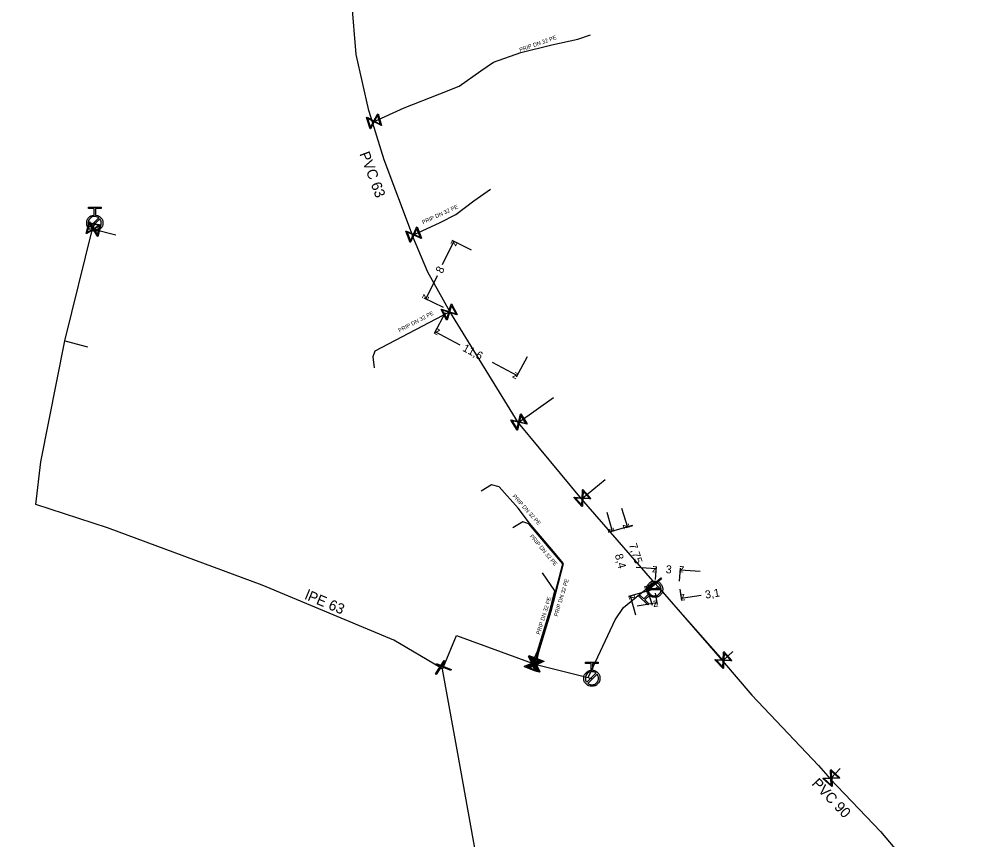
# Model space of a CAD drawing. Extents: x -641905 to -641246, y -1111750 to -1110210.
# Drawn here: x -641580.5 to -641459.9, y -1110405.6 to -1110303.2 of the extents above; entities that cross this region are included whole.
import ezdxf

# ---------------------------------------------------------------- set-up
doc = ezdxf.new("R2010")
doc.units = 0
for name, color, linetype in [('Default', 7, 'Continuous'), ('VP Hydrant', 7, 'Continuous'), ('VP Kótování', 7, 'Continuous'), ('VP Popis přípojky', 7, 'Continuous'), ('VP Přípojka', 7, 'Continuous'), ('VP Řad', 7, 'Continuous'), ('VP Řad - popis', 7, 'Continuous'), ('VP Šoupě', 7, 'Continuous')]:
    doc.layers.add(name, color=color, linetype=linetype)

msp = doc.modelspace()

# ---------------------------------------------------------------- linework, layer by layer
at = {"layer": 'Default'}
for points in [[(-641571, -1110327.63), (-641570.64, -1110327.66), (-641570.38, -1110327.92), (-641570.09, -1110328.21), (-641570.09, -1110328.63), (-641570.09, -1110329.04), (-641570.39, -1110329.34), (-641570.68, -1110329.63), (-641571.09, -1110329.63), (-641571.51, -1110329.63), (-641571.8, -1110329.34), (-641572.09, -1110329.04), (-641572.09, -1110328.63), (-641572.09, -1110328.21), (-641571.8, -1110327.92), (-641571.54, -1110327.66), (-641571.18, -1110327.63)], [(-641570.59, -1110327.99), (-641570.8, -1110327.81), (-641571.09, -1110327.81), (-641571.43, -1110327.81), (-641571.67, -1110328.05), (-641571.91, -1110328.29), (-641571.91, -1110328.63), (-641571.91, -1110328.92), (-641571.73, -1110329.13)], [(-641571.6, -1110329.26), (-641571.38, -1110329.44), (-641571.09, -1110329.44), (-641570.76, -1110329.44), (-641570.52, -1110329.2), (-641570.28, -1110328.96), (-641570.28, -1110328.63), (-641570.28, -1110328.34), (-641570.46, -1110328.12)], [(-641501.93, -1110374.99), (-641502.16, -1110374.72), (-641502.16, -1110374.35), (-641502.16, -1110373.94), (-641501.86, -1110373.64), (-641501.57, -1110373.35), (-641501.16, -1110373.35), (-641500.74, -1110373.36), (-641500.45, -1110373.65), (-641500.16, -1110373.94), (-641500.16, -1110374.36), (-641500.16, -1110374.77), (-641500.45, -1110375.06), (-641500.75, -1110375.36), (-641501.16, -1110375.36), (-641501.53, -1110375.36), (-641501.8, -1110375.12)], [(-641500.35, -1110374.27), (-641500.38, -1110373.99), (-641500.58, -1110373.78), (-641500.82, -1110373.55), (-641501.16, -1110373.54), (-641501.49, -1110373.54), (-641501.73, -1110373.78), (-641501.94, -1110373.99), (-641501.97, -1110374.26)], [(-641501.97, -1110374.44), (-641501.94, -1110374.72), (-641501.74, -1110374.93), (-641501.5, -1110375.17), (-641501.16, -1110375.17), (-641500.83, -1110375.17), (-641500.59, -1110374.93), (-641500.38, -1110374.73), (-641500.35, -1110374.45)], [(-641508.91, -1110384.47), (-641508.55, -1110384.5), (-641508.29, -1110384.76), (-641508, -1110385.06), (-641508, -1110385.47), (-641508, -1110385.89), (-641508.29, -1110386.18), (-641508.59, -1110386.47), (-641509, -1110386.47), (-641509.41, -1110386.47), (-641509.71, -1110386.18), (-641510, -1110385.89), (-641510, -1110385.47), (-641510, -1110385.06), (-641509.71, -1110384.76), (-641509.45, -1110384.5), (-641509.09, -1110384.47)], [(-641508.49, -1110384.83), (-641508.71, -1110384.66), (-641509, -1110384.66), (-641509.34, -1110384.66), (-641509.58, -1110384.89), (-641509.81, -1110385.13), (-641509.81, -1110385.47), (-641509.81, -1110385.76), (-641509.64, -1110385.98)], [(-641509.51, -1110386.11), (-641509.29, -1110386.28), (-641509, -1110386.28), (-641508.67, -1110386.28), (-641508.43, -1110386.04), (-641508.19, -1110385.81), (-641508.19, -1110385.47), (-641508.19, -1110385.18), (-641508.36, -1110384.96)]]:
    msp.add_open_spline(points, degree=3, dxfattribs=at)
at = {"layer": 'VP Hydrant'}
for points in [[(-641571.18, -1110327.63), (-641571.18, -1110326.81), (-641571.87, -1110326.81), (-641571.87, -1110326.63), (-641570.31, -1110326.63), (-641570.31, -1110326.81), (-641571, -1110326.81), (-641571, -1110327.63)], [(-641571.73, -1110329.13), (-641570.59, -1110327.99)], [(-641570.46, -1110328.12), (-641571.6, -1110329.26)], [(-641501.97, -1110374.26), (-641500.35, -1110374.27)], [(-641500.35, -1110374.45), (-641501.97, -1110374.44)], [(-641501.8, -1110375.12), (-641502.38, -1110375.7), (-641501.9, -1110376.19), (-641502.03, -1110376.32), (-641503.13, -1110375.21), (-641503, -1110375.08), (-641502.51, -1110375.57), (-641501.93, -1110374.99)], [(-641509.09, -1110384.47), (-641509.09, -1110383.65), (-641509.78, -1110383.65), (-641509.78, -1110383.47), (-641508.22, -1110383.47), (-641508.22, -1110383.65), (-641508.91, -1110383.65), (-641508.91, -1110384.47)], [(-641509.64, -1110385.98), (-641508.49, -1110384.83)], [(-641508.36, -1110384.96), (-641509.51, -1110386.11)]]:
    msp.add_lwpolyline(points, dxfattribs=at)
at = {"layer": 'VP Kótování'}
for points in [[(-641527.65, -1110333.8), (-641526.24, -1110330.92)], [(-641524.02, -1110332), (-641526.47, -1110330.81)], [(-641528.34, -1110335.23), (-641529.75, -1110338.11)], [(-641527.52, -1110339.19), (-641529.97, -1110338)], [(-641527.31, -1110339.85), (-641528.68, -1110342.42)], [(-641525.46, -1110343.86), (-641528.56, -1110342.2)], [(-641517.08, -1110345.32), (-641518.45, -1110347.89)], [(-641521.44, -1110346.01), (-641518.33, -1110347.67)], [(-641507.14, -1110364.72), (-641506.46, -1110367.12)], [(-641505.3, -1110364.24), (-641504.54, -1110366.62)], [(-641503.92, -1110366.41), (-641506.7, -1110367.19)], [(-641503.92, -1110366.42), (-641504.78, -1110366.7)], [(-641503.46, -1110371.59), (-641500.96, -1110371.76)], [(-641501.06, -1110373.16), (-641500.95, -1110371.52)], [(-641498.07, -1110373.36), (-641497.95, -1110371.72)], [(-641495.48, -1110372.14), (-641497.97, -1110371.97)], [(-641501.64, -1110374.49), (-641504.42, -1110375.27)], [(-641501.57, -1110373.81), (-641502.44, -1110374.08)], [(-641501.44, -1110376.39), (-641502.2, -1110374.01)], [(-641498.02, -1110374.35), (-641497.79, -1110375.77)], [(-641503.5, -1110377.61), (-641504.18, -1110375.21)], [(-641501.08, -1110374.85), (-641500.85, -1110376.26)], [(-641495.36, -1110375.12), (-641497.83, -1110375.52)], [(-641503.36, -1110376.42), (-641500.89, -1110376.02)]]:
    msp.add_lwpolyline(points, dxfattribs=at)
at = {"layer": 'VP Přípojka'}
for points in [[(-641536.4, -1110316.01), (-641536.21, -1110315.93), (-641532.46, -1110314.25), (-641528.01, -1110312.5), (-641525.58, -1110311.52), (-641522.87, -1110309.6), (-641521.28, -1110308.52), (-641517.88, -1110307.31), (-641514, -1110306.36), (-641510.76, -1110305.68), (-641509.19, -1110305.14)], [(-641531.42, -1110330.15), (-641531.27, -1110330.09), (-641527.94, -1110328.56), (-641526, -1110327.54), (-641523.75, -1110325.87), (-641521.67, -1110324.38)], [(-641571.14, -1110328.81), (-641571.13, -1110328.76), (-641571.1, -1110328.62)], [(-641571.39, -1110329.35), (-641571.25, -1110329.38), (-641568.48, -1110330.11)], [(-641526.74, -1110339.69), (-641526.83, -1110339.74), (-641536.12, -1110344.64), (-641536.37, -1110345.33), (-641536.18, -1110346.69)], [(-641574.84, -1110343.34), (-641574.68, -1110343.39), (-641572, -1110344.07)], [(-641518.19, -1110353.53), (-641518.11, -1110353.48), (-641513.79, -1110350.4)], [(-641515.97, -1110383.76), (-641515.61, -1110382.16), (-641514.07, -1110377.1), (-641512.53, -1110371.15), (-641514.26, -1110369.12), (-641516.81, -1110366.09), (-641518.21, -1110364.22), (-641520.59, -1110361.58), (-641521.53, -1110361.33), (-641522.82, -1110362.09)], [(-641510.28, -1110363.07), (-641510.18, -1110362.98), (-641507.36, -1110360.66)], [(-641516.18, -1110383.71), (-641515.71, -1110382.15), (-641514.17, -1110377.07), (-641512.64, -1110371.18), (-641514.34, -1110369.18), (-641516.87, -1110366.18), (-641517.64, -1110365.95), (-641518.87, -1110366.68)], [(-641516.46, -1110383.61), (-641515.81, -1110382.1), (-641514.26, -1110377.04), (-641513.64, -1110374.55), (-641515.19, -1110372.31)], [(-641501.23, -1110373.51), (-641501.09, -1110373.66), (-641492.62, -1110383.25)], [(-641500.78, -1110374.02), (-641501.16, -1110374.35)], [(-641492.67, -1110383.28), (-641492.57, -1110383.21), (-641491.41, -1110382.15)], [(-641509.46, -1110385.39), (-641509.26, -1110385.47), (-641509, -1110385.47)], [(-641479.24, -1110398.03), (-641479.1, -1110397.95), (-641478, -1110396.74)]]:
    msp.add_lwpolyline(points, dxfattribs=at)
at = {"layer": 'VP Řad'}
for points in [[(-641527.66, -1110384.33), (-641527.53, -1110384.09), (-641527.52, -1110384.06), (-641525.91, -1110380.13), (-641516.46, -1110383.61), (-641516.18, -1110383.71), (-641515.97, -1110383.76), (-641509.46, -1110385.39), (-641506.08, -1110378.16), (-641505.04, -1110376.65), (-641501.23, -1110373.51), (-641501.31, -1110373.41), (-641501.39, -1110373.32), (-641510.28, -1110363.07), (-641518.16, -1110353.57), (-641518.19, -1110353.53), (-641526.74, -1110339.69), (-641529.48, -1110334.78), (-641531.39, -1110330.24), (-641531.42, -1110330.15), (-641534.94, -1110320.75), (-641536.4, -1110316.01), (-641536.84, -1110314.59), (-641538.45, -1110307.59), (-641539, -1110300.99)], [(-641527.66, -1110384.33), (-641527.95, -1110384.14), (-641533.74, -1110380.7), (-641550.18, -1110373.84), (-641569.5, -1110366.69), (-641578.47, -1110363.78), (-641577.82, -1110358.43), (-641574.84, -1110343.34), (-641571.39, -1110329.35), (-641571.14, -1110328.81)], [(-641501.23, -1110373.51), (-641501.1, -1110373.66), (-641500.78, -1110374.02), (-641492.67, -1110383.28), (-641489.03, -1110387.57), (-641480.69, -1110396.36), (-641479.24, -1110398.03), (-641472.94, -1110404.61), (-641468.24, -1110410.18), (-641464.28, -1110416.05), (-641461.19, -1110422.75), (-641460.59, -1110426.23), (-641459.94, -1110433), (-641461.33, -1110445.88), (-641461.34, -1110445.94), (-641462.79, -1110455.16), (-641463.43, -1110458.76), (-641464.01, -1110462.8), (-641464.58, -1110466.76), (-641467.61, -1110476.11), (-641469.87, -1110480.96), (-641471.29, -1110483.79), (-641472.59, -1110486.61)], [(-641664.58, -1110640.46), (-641633.71, -1110609.9), (-641600.63, -1110563.76), (-641598.45, -1110560.36), (-641594.73, -1110553.8), (-641592.83, -1110550.42), (-641585.04, -1110537.85), (-641581.85, -1110531.99), (-641576.72, -1110525.41), (-641572.32, -1110520.62), (-641569.27, -1110517.47), (-641555.1, -1110505.43), (-641544.01, -1110494.76), (-641533.36, -1110480.93), (-641531.9, -1110478.13), (-641529.81, -1110469.31), (-641527.31, -1110459.48), (-641524.97, -1110448.07), (-641523.07, -1110437.29), (-641521.61, -1110424.89), (-641523.18, -1110409.24), (-641525.76, -1110394.87), (-641527.66, -1110384.33)]]:
    msp.add_lwpolyline(points, dxfattribs=at)
at = {"layer": 'VP Šoupě'}
for points in [[(-641535.71, -1110314.99), (-641535.27, -1110316.43), (-641535.34, -1110316.45), (-641535.45, -1110316.38), (-641536.19, -1110315.99), (-641536.64, -1110316.85), (-641536.71, -1110316.87), (-641537.15, -1110315.43), (-641537.08, -1110315.41), (-641536.23, -1110315.87), (-641535.83, -1110315.13), (-641535.78, -1110315.01), (-641535.71, -1110314.99)], [(-641536.66, -1110316.69), (-641536.27, -1110315.95), (-641537.01, -1110315.56), (-641536.66, -1110316.69)], [(-641535.76, -1110315.17), (-641536.15, -1110315.91), (-641535.41, -1110316.3), (-641535.76, -1110315.17)], [(-641570.34, -1110328.83), (-641570.7, -1110330.29), (-641570.76, -1110330.27), (-641570.83, -1110330.16), (-641571.26, -1110329.44), (-641572.09, -1110329.95), (-641572.16, -1110329.93), (-641571.8, -1110328.47), (-641571.74, -1110328.49), (-641571.23, -1110329.32), (-641570.52, -1110328.88), (-641570.41, -1110328.81), (-641570.34, -1110328.83)], [(-641572.03, -1110329.8), (-641571.31, -1110329.37), (-641571.75, -1110328.65), (-641572.03, -1110329.8)], [(-641571.85, -1110328.56), (-641570.39, -1110328.87), (-641570.41, -1110328.96), (-641571.87, -1110328.65), (-641571.85, -1110328.56)], [(-641570.47, -1110328.96), (-641571.19, -1110329.4), (-641570.75, -1110330.11), (-641570.47, -1110328.96)], [(-641530.83, -1110329.12), (-641530.3, -1110330.53), (-641530.37, -1110330.55), (-641530.48, -1110330.49), (-641531.25, -1110330.15), (-641531.65, -1110331.03), (-641531.71, -1110331.06), (-641532.24, -1110329.65), (-641532.17, -1110329.63), (-641531.29, -1110330.03), (-641530.94, -1110329.27), (-641530.89, -1110329.15), (-641530.83, -1110329.12)], [(-641531.67, -1110330.88), (-641531.33, -1110330.11), (-641532.09, -1110329.77), (-641531.67, -1110330.88)], [(-641530.86, -1110329.3), (-641531.21, -1110330.07), (-641530.45, -1110330.41), (-641530.86, -1110329.3)], [(-641526.52, -1110338.73), (-641525.82, -1110340.05), (-641525.88, -1110340.08), (-641526, -1110340.04), (-641526.8, -1110339.8), (-641527.09, -1110340.72), (-641527.14, -1110340.75), (-641527.84, -1110339.43), (-641527.79, -1110339.4), (-641526.86, -1110339.69), (-641526.61, -1110338.88), (-641526.57, -1110338.76), (-641526.52, -1110338.73)], [(-641527.13, -1110340.58), (-641526.88, -1110339.77), (-641527.69, -1110339.52), (-641527.13, -1110340.58)], [(-641526.53, -1110338.91), (-641526.77, -1110339.71), (-641525.97, -1110339.96), (-641526.53, -1110338.91)], [(-641517.87, -1110352.45), (-641517.08, -1110353.72), (-641517.13, -1110353.76), (-641517.26, -1110353.72), (-641518.08, -1110353.53), (-641518.3, -1110354.48), (-641518.35, -1110354.51), (-641519.14, -1110353.24), (-641519.09, -1110353.2), (-641518.14, -1110353.43), (-641517.95, -1110352.61), (-641517.92, -1110352.48), (-641517.87, -1110352.45)], [(-641517.86, -1110352.63), (-641518.06, -1110353.45), (-641517.24, -1110353.64), (-641517.86, -1110352.63)], [(-641518.35, -1110354.33), (-641518.16, -1110353.51), (-641518.98, -1110353.32), (-641518.35, -1110354.33)], [(-641510.12, -1110361.92), (-641509.12, -1110363.04), (-641509.17, -1110363.08), (-641509.3, -1110363.07), (-641510.14, -1110363.03), (-641510.19, -1110363.99), (-641510.24, -1110364.04), (-641511.24, -1110362.92), (-641511.19, -1110362.88), (-641510.22, -1110362.93), (-641510.18, -1110362.09), (-641510.17, -1110361.96), (-641510.12, -1110361.92)], [(-641510.09, -1110362.1), (-641510.13, -1110362.94), (-641509.3, -1110362.98), (-641510.09, -1110362.1)], [(-641510.27, -1110363.86), (-641510.22, -1110363.02), (-641511.06, -1110362.98), (-641510.27, -1110363.86)], [(-641500.3, -1110373.04), (-641501.8, -1110374.37), (-641501.88, -1110374.27), (-641500.39, -1110372.95), (-641500.3, -1110373.04)], [(-641516.89, -1110382.64), (-641515.49, -1110383.18), (-641515.51, -1110383.24), (-641515.63, -1110383.29), (-641516.4, -1110383.63), (-641516.01, -1110384.52), (-641516.03, -1110384.58), (-641517.43, -1110384.04), (-641517.41, -1110383.98), (-641516.52, -1110383.59), (-641516.86, -1110382.82), (-641516.91, -1110382.7), (-641516.89, -1110382.64)], [(-641516.61, -1110382.74), (-641515.21, -1110383.28), (-641515.23, -1110383.34), (-641515.35, -1110383.39), (-641516.12, -1110383.73), (-641515.73, -1110384.62), (-641515.75, -1110384.68), (-641517.15, -1110384.14), (-641517.13, -1110384.08), (-641516.24, -1110383.69), (-641516.58, -1110382.92), (-641516.63, -1110382.8), (-641516.61, -1110382.74)], [(-641516.4, -1110382.79), (-641515, -1110383.33), (-641515.02, -1110383.39), (-641515.14, -1110383.44), (-641515.91, -1110383.78), (-641515.52, -1110384.67), (-641515.54, -1110384.73), (-641516.94, -1110384.19), (-641516.92, -1110384.13), (-641516.03, -1110383.74), (-641516.37, -1110382.97), (-641516.42, -1110382.85), (-641516.4, -1110382.79)], [(-641516.78, -1110382.78), (-641516.44, -1110383.55), (-641515.67, -1110383.21), (-641516.78, -1110382.78)], [(-641516.5, -1110382.88), (-641516.16, -1110383.65), (-641515.39, -1110383.31), (-641516.5, -1110382.88)], [(-641516.29, -1110382.93), (-641515.95, -1110383.7), (-641515.18, -1110383.36), (-641516.29, -1110382.93)], [(-641492.53, -1110382.15), (-641491.51, -1110383.25), (-641491.56, -1110383.3), (-641491.69, -1110383.29), (-641492.53, -1110383.26), (-641492.57, -1110384.23), (-641492.61, -1110384.27), (-641493.63, -1110383.17), (-641493.58, -1110383.12), (-641492.61, -1110383.16), (-641492.58, -1110382.32), (-641492.57, -1110382.2), (-641492.53, -1110382.15)], [(-641492.65, -1110384.09), (-641492.61, -1110383.25), (-641493.45, -1110383.22), (-641492.65, -1110384.09)], [(-641492.49, -1110382.33), (-641492.52, -1110383.17), (-641491.69, -1110383.2), (-641492.49, -1110382.33)], [(-641527.35, -1110383.34), (-641528.45, -1110385.01), (-641528.55, -1110384.94), (-641527.45, -1110383.27), (-641527.35, -1110383.34)], [(-641528.42, -1110383.63), (-641526.57, -1110384.38), (-641526.62, -1110384.5), (-641528.47, -1110383.74), (-641528.42, -1110383.63)], [(-641516.14, -1110384.44), (-641516.48, -1110383.67), (-641517.25, -1110384.01), (-641516.14, -1110384.44)], [(-641515.86, -1110384.54), (-641516.2, -1110383.77), (-641516.97, -1110384.11), (-641515.86, -1110384.54)], [(-641515.65, -1110384.59), (-641515.99, -1110383.82), (-641516.76, -1110384.16), (-641515.65, -1110384.59)], [(-641479.15, -1110396.89), (-641478.04, -1110397.9), (-641478.09, -1110397.95), (-641478.21, -1110397.95), (-641479.05, -1110397.99), (-641479.01, -1110398.96), (-641479.05, -1110399.01), (-641480.16, -1110398), (-641480.12, -1110397.95), (-641479.14, -1110397.91), (-641479.18, -1110397.07), (-641479.19, -1110396.94), (-641479.15, -1110396.89)], [(-641479.1, -1110397.07), (-641479.06, -1110397.9), (-641478.22, -1110397.86), (-641479.1, -1110397.07)], [(-641479.1, -1110398.84), (-641479.14, -1110398), (-641479.98, -1110398.03), (-641479.1, -1110398.84)]]:
    msp.add_lwpolyline(points, dxfattribs=at)

# ---------------------------------------------------------------- texts
at = {"layer": 'VP Kótování'}
for s, rotation, p in [('z', 64.0248, (-641526.01, -1110331.59)), ('8', 64.0248, (-641527.68, -1110335)), ('z', 244.0248, (-641529.98, -1110337.44)), ('z', 151.881, (-641527.89, -1110342)), ('11,6', 331.881, (-641525.25, -1110344.54)), ('z', 331.881, (-641519.01, -1110347.87)), ('z', 287.6277, (-641505.17, -1110366.3)), ('z', 285.7474, (-641507.08, -1110366.78)), ('7,75', 287.6277, (-641504.38, -1110368.79)), ('8,4', 285.7474, (-641506.15, -1110370.08)), ('z', 356.1027, (-641501.5, -1110372.23)), ('3', 356.1027, (-641499.8, -1110372.35)), ('z', 176.1027, (-641497.44, -1110371.5)), ('z', 107.6277, (-641501.57, -1110374.33)), ('3,1', 9.1831, (-641494.79, -1110375.54)), ('z', 105.7474, (-641503.56, -1110375.55)), ('z', 9.1831, (-641501.31, -1110376.59)), ('z', 189.1831, (-641497.42, -1110374.95))]:
    msp.add_text(s, height=1, rotation=rotation, dxfattribs=at).set_placement(p)
at = {"layer": 'VP Popis přípojky'}
for rotation, p in [(19.5898, (-641517.96, -1110307.27)), (24.6769, (-641530.09, -1110328.79)), (27.8094, (-641533.02, -1110342.3)), (312.0351, (-641518.96, -1110362.77)), (310.142, (-641516.79, -1110367.77)), (73.0725, (-641513.29, -1110377.8)), (72.9689, (-641515.49, -1110380.06))]:
    msp.add_text('PRIP DN 32 PE', height=0.5, rotation=rotation, dxfattribs=at).set_placement(p)
at = {"layer": 'VP Řad - popis'}
for s, rotation, p in [('PVC 63', 290.5097, (-641538.05, -1110319.98)), ('lPE 63', 337.3504, (-641544.96, -1110375.56)), ('PVC 90', 313.7546, (-641481.62, -1110398.71))]:
    msp.add_text(s, height=1.3, rotation=rotation, dxfattribs=at).set_placement(p)

doc.saveas('drawing.dxf')
